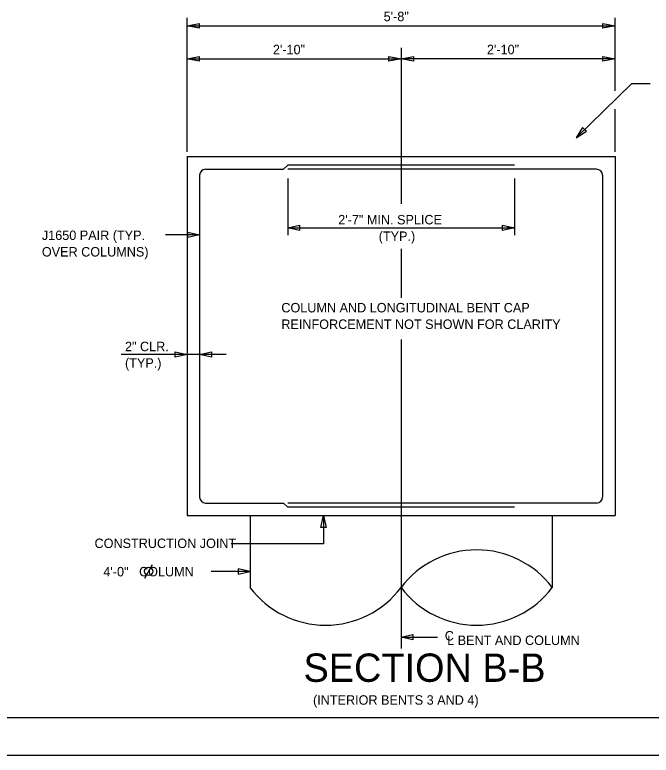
# Model space of a CAD drawing. Extents: x -133.1 to -97, y -1.7 to 20.3.
# Drawn here: x -118.94 to -110.52, y -1.69 to 8.11 of the extents above; entities that cross this region are included whole.
import ezdxf

# ---------------------------------------------------------------- set-up
doc = ezdxf.new("R2010")
doc.units = 0
for name, color, linetype in [('BR_AUTO DIMENSION', 7, 'Continuous'), ('BR_BORDER LINES', 7, 'Continuous'), ('BR_CENTER LINES', 7, 'Continuous'), ('BR_CONCRETE', 7, 'Continuous'), ('BR_REBAR', 7, 'Continuous'), ('BR_TEXT', 7, 'Continuous'), ('Level 31', 7, 'Continuous')]:
    doc.layers.add(name, color=color, linetype=linetype)

msp = doc.modelspace()

# ---------------------------------------------------------------- linework, layer by layer
at = {"layer": 'BR_AUTO DIMENSION'}
for p, q in [((-116.6642, 6.2918), (-116.6642, 8.0663)), ((-110.9975, 7.1017), (-110.9975, 8.0663)), ((-116.6642, 7.9586), (-110.9975, 7.9586)), ((-116.6642, 7.5218), (-113.8308, 7.5218)), ((-110.9975, 7.5218), (-113.8308, 7.5218)), ((-110.9975, 6.2918), (-110.9975, 6.8571)), ((-115.3308, 5.9419), (-115.3308, 5.1885)), ((-112.3308, 5.9419), (-112.3308, 5.1885)), ((-116.4975, 5.1951), (-116.9512, 5.1951)), ((-115.3308, 5.286), (-112.3308, 5.286)), ((-116.1461, 3.6105), (-117.5384, 3.6105)), ((-114.8578, 1.4793), (-114.8578, 1.1065)), ((-114.8578, 1.1065), (-116.0816, 1.1065)), ((-115.8309, 0.7383), (-116.3429, 0.7383)), ((-113.8309, -0.1278), (-113.3481, -0.1278))]:
    msp.add_line(p, q, dxfattribs=at)
for points in [[(-116.5017, 7.9274), (-116.6642, 7.9586), (-116.5017, 7.9899)], [(-111.16, 7.9899), (-110.9975, 7.9586), (-111.16, 7.9274)], [(-116.5017, 7.4906), (-116.6642, 7.5218), (-116.5017, 7.5531)], [(-113.9933, 7.5531), (-113.8308, 7.5218), (-113.9933, 7.4906)], [(-113.6683, 7.4906), (-113.8308, 7.5218), (-113.6683, 7.5531)], [(-111.16, 7.5531), (-110.9975, 7.5218), (-111.16, 7.4906)], [(-111.4294, 6.6164), (-111.5115, 6.479), (-111.3774, 6.5665)], [(-115.1748, 5.25), (-115.3308, 5.286), (-115.1748, 5.322)], [(-112.4868, 5.322), (-112.3308, 5.286), (-112.4868, 5.25)], [(-116.6535, 5.2311), (-116.4975, 5.1951), (-116.6535, 5.1591)], [(-116.8201, 3.6465), (-116.6642, 3.6105), (-116.8201, 3.5745)], [(-116.3415, 3.5745), (-116.4975, 3.6105), (-116.3415, 3.6465)], [(-114.8938, 1.3233), (-114.8578, 1.4793), (-114.8218, 1.3233)], [(-115.9869, 0.7023), (-115.8309, 0.7383), (-115.9869, 0.7743)], [(-113.6749, -0.1638), (-113.8309, -0.1278), (-113.6749, -0.0918)]]:
    msp.add_lwpolyline(points, close=True, dxfattribs=at)
msp.add_lwpolyline([(-111.5115, 6.479), (-110.7772, 7.1951), (-110.5329, 7.1951)], dxfattribs=at)
at = {"layer": 'BR_BORDER LINES'}
msp.add_line((-131.3076, -1.191), (-97.6416, -1.191), dxfattribs=at)
at = {"layer": 'BR_CENTER LINES'}
for p, q in [((-113.8308, 7.6694), (-113.8308, 5.6055)), ((-113.8308, 5.0111), (-113.8308, 4.3627)), ((-113.8308, 3.8083), (-113.8309, -0.2781))]:
    msp.add_line(p, q, dxfattribs=at)
at = {"layer": 'BR_CONCRETE'}
for p, q in [((-116.6642, 6.2293), (-116.6642, 1.4793)), ((-116.6642, 6.2293), (-110.9975, 6.2293)), ((-110.9975, 6.2293), (-110.9975, 1.4793)), ((-116.6642, 1.4793), (-115.8309, 1.4793)), ((-115.8309, 1.4793), (-111.8309, 1.4793)), ((-115.8309, 1.4793), (-115.8309, 0.5277)), ((-111.8309, 1.4793), (-110.9975, 1.4793)), ((-111.8309, 1.4793), (-111.8309, 0.5277))]:
    msp.add_line(p, q, dxfattribs=at)
for centre, start, end in [((-112.8309, -0.226), 37.00228, 142.99772), ((-114.8309, 1.2813), 217.00228, 322.99772), ((-112.8309, 1.2813), 217.00228, 322.99772)]:
    msp.add_arc(centre, 1.2522, start, end, dxfattribs=at)
at = {"layer": 'BR_REBAR'}
for p, q in [((-115.3863, 6.0627), (-115.3308, 6.1181)), ((-112.3308, 6.1181), (-115.3308, 6.1181)), ((-116.4975, 5.9845), (-116.4975, 1.7241)), ((-116.4194, 6.0627), (-115.3863, 6.0627)), ((-111.242, 6.0627), (-115.3308, 6.0627)), ((-111.1642, 5.9845), (-111.1642, 1.7241)), ((-116.4194, 1.646), (-115.3863, 1.646)), ((-115.3863, 1.646), (-115.3308, 1.5905)), ((-111.2423, 1.646), (-115.3308, 1.646)), ((-112.3308, 1.5905), (-115.3308, 1.5905))]:
    msp.add_line(p, q, dxfattribs=at)
for centre, start, end in [((-116.4194, 5.9845), 90, 180), ((-111.2423, 5.9845), 360, 90), ((-116.4194, 1.7241), 180, 270), ((-111.2423, 1.7241), 270, 360)]:
    msp.add_arc(centre, 0.0781, start, end, dxfattribs=at)
at = {"layer": 'BR_TEXT'}
for p, q in [((-115.3308, 5.286), (-115.2535, 5.286)), ((-112.3308, 5.286), (-112.428, 5.286)), ((-117.225, 0.6505), (-117.12, 0.8324))]:
    msp.add_line(p, q, dxfattribs=at)
msp.add_circle((-117.1725, 0.7414), 0.055, dxfattribs=at)
at = {"layer": 'Level 31'}
msp.add_lwpolyline([(-133.1409, -1.691), (-97.141, -1.691), (-97.141, 20.309), (-133.1409, 20.309)], close=True, dxfattribs=at)

# ---------------------------------------------------------------- texts
at = {"layer": 'BR_AUTO DIMENSION'}
for s, p in [('5\'-8"', (-114.0615, 8.0211)), ('2\'-10"', (-115.5278, 7.5843)), ('2\'-10"', (-112.6945, 7.5843))]:
    msp.add_text(s, height=0.125, dxfattribs=at).set_placement(p)
at = {"layer": 'BR_TEXT'}
for s, height, p in [('2\'-7" MIN. SPLICE', 0.125002, (-114.6627, 5.3329)), ('J1650 PAIR (TYP.', 0.125002, (-118.5859, 5.1264)), ('(TYP.)', 0.125, (-114.1272, 5.1141)), ('OVER COLUMNS)', 0.125002, (-118.5859, 4.9077)), ('COLUMN AND LONGITUDINAL BENT CAP', 0.125002, (-115.416, 4.1683)), ('REINFORCEMENT NOT SHOWN FOR CLARITY', 0.125002, (-115.416, 3.9496)), ('2" CLR.', 0.125, (-117.4859, 3.655)), ('(TYP.)', 0.125, (-117.4859, 3.4363)), ('CONSTRUCTION JOINT', 0.125002, (-117.8888, 1.0503)), ('4\'-0"   COLUMN', 0.125002, (-117.7719, 0.6753)), ('C', 0.125, (-113.2526, -0.1735)), ('L BENT AND COLUMN', 0.125002, (-113.2211, -0.2328)), ('(INTERIOR BENTS 3 AND 4)', 0.125002, (-114.9966, -1.0229))]:
    msp.add_text(s, height=height, rotation=360, dxfattribs=at).set_placement(p)
msp.add_text('SECTION B-B', height=0.375005, dxfattribs=at).set_placement((-115.1227, -0.7204))

doc.saveas('drawing.dxf')
